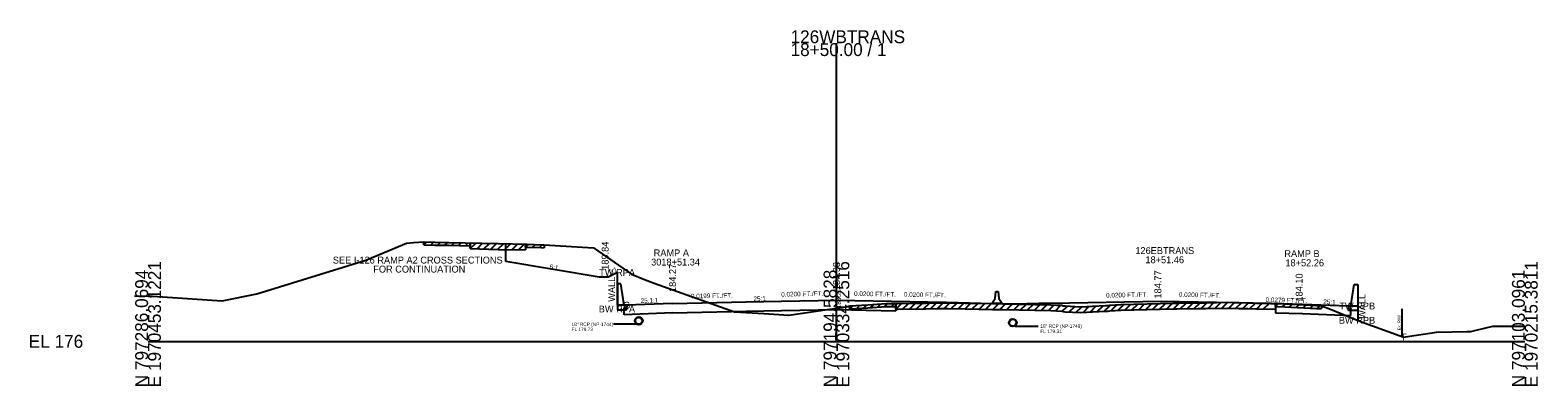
# Model space of a CAD drawing. Extents: x -6494 to 1970605, y -10 to 798140.
# Drawn here: x 974.3 to 1302.8, y 990.3 to 1067.8 of the extents above; entities that cross this region are included whole.
import ezdxf

# ---------------------------------------------------------------- set-up
doc = ezdxf.new("R2010")
doc.units = 0
for name, color, linetype in [('Default', 7, 'Continuous'), ('RD_EX_SU_Misc_TxCode', 7, 'Continuous'), ('RD_GPK_XS_Cell', 7, 'Continuous'), ('RD_Sketch1', 7, 'Continuous'), ('RD_XS_Base', 7, 'Continuous'), ('RD_XS_Box', 7, 'Continuous'), ('RD_XS_EwShp', 7, 'Continuous'), ('RD_XS_ExGround', 7, 'Continuous'), ('RD_XS_ExPaveRet', 7, 'Continuous'), ('RD_XS_ExRW', 7, 'Continuous'), ('RD_XS_MedBWall', 7, 'Continuous'), ('RD_XS_Misc_Line', 7, 'Continuous'), ('RD_XS_Pave', 7, 'Continuous'), ('RD_XS_PaveOvlay', 7, 'Continuous'), ('RD_XS_PaveShd', 7, 'Continuous'), ('RD_XS_Pipe', 7, 'Continuous'), ('RD_XS_TieSlope', 7, 'Continuous'), ('RD_XS_TX_Elev_EX', 7, 'Continuous'), ('RD_XS_TX_Elev_PR', 7, 'Continuous'), ('RD_XS_TX_Misc', 7, 'Continuous'), ('RD_XS_TX_Notes', 7, 'Continuous'), ('RD_XS_TX_Profile', 7, 'Continuous'), ('RD_XS_TX_Slope', 7, 'Continuous'), ('RD_XS_TX_Station', 7, 'Continuous')]:
    doc.layers.add(name, color=color, linetype=linetype)

msp = doc.modelspace()

# ---------------------------------------------------------------- linework, layer by layer
at = {"layer": 'Default'}
for p, q in [((1184, 1008.47), (1184.58, 1009.31)), ((1184.58, 1009.31), (1184.75, 1010.89)), ((1184.75, 1010.89), (1185.25, 1010.89)), ((1185.25, 1010.89), (1185.42, 1009.31)), ((1185.42, 1009.31), (1186, 1008.47)), ((1184, 1008.22), (1184, 1008.47)), ((1186, 1008.22), (1184, 1008.22)), ((1186, 1008.47), (1186, 1008.22))]:
    msp.add_line(p, q, dxfattribs=at)
at = {"layer": 'RD_GPK_XS_Cell'}
for p, q in [((1150, 1000), (1150, 1064.95)), ((1000, 1000), (1150, 1000)), ((1150, 1000), (1300, 1000))]:
    msp.add_line(p, q, dxfattribs=at)
at = {"layer": 'RD_XS_Base'}
for p, q in [((1103.77, 1007.29), (1104.28, 1007.31)), ((1103.77, 1005.81), (1103.77, 1007.29)), ((1114.3, 1006.23), (1103.77, 1005.81)), ((1104.28, 1007.31), (1104.28, 1007.87)), ((1114.3, 1006.23), (1130.33, 1006.55)), ((1130.33, 1006.55), (1138, 1006.7)), ((1138, 1006.7), (1150, 1006.94)), ((1150, 1006.94), (1162.92, 1006.68)), ((1245.7, 1006.21), (1251.57, 1006.06)), ((1251.57, 1006.06), (1262.1, 1005.64)), ((1261.6, 1007.14), (1261.6, 1007.7)), ((1262.1, 1007.12), (1261.6, 1007.14)), ((1262.1, 1005.64), (1262.1, 1007.12))]:
    msp.add_line(p, q, dxfattribs=at)
at = {"layer": 'RD_XS_Box'}
for p, q in [((1102.28, 1007.87), (1102.28, 1015)), ((1104.28, 1007.87), (1102.28, 1007.87)), ((1261.6, 1007.7), (1263.61, 1007.7)), ((1263.61, 1007.7), (1263.61, 1004.58))]:
    msp.add_line(p, q, dxfattribs=at)
at = {"layer": 'RD_XS_ExGround'}
msp.add_line((997.08, 1009.94), (1000, 1009.87), dxfattribs=at)
msp.add_lwpolyline([(1000, 1009.87), (1000.98, 1009.84), (1003.17, 1009.67), (1016.17, 1008.8), (1023.73, 1010.34), (1047.47, 1017.67), (1056.29, 1021.38), (1057.85, 1021.5), (1060.08, 1021.65), (1062.51, 1021.58), (1065.54, 1021.55), (1076.29, 1021.29), (1082.58, 1021.14), (1085.68, 1021.04), (1086.29, 1021.02), (1089.89, 1020.8), (1097.09, 1020.38), (1105.34, 1014.65), (1108.19, 1013.45), (1110.28, 1012.7), (1127.79, 1006.41), (1134.16, 1006.04), (1139.6, 1005.68), (1148.05, 1006.96), (1150, 1007.21), (1151.32, 1007.38), (1152.92, 1007.71), (1156.84, 1007.96), (1160.86, 1008.22), (1163.28, 1008.25), (1169.45, 1008.33), (1172.38, 1008.39), (1173.22, 1008.41), (1174.35, 1008.39), (1178.05, 1008.32), (1184.04, 1008.22), (1184.94, 1008.21), (1186.27, 1008.18), (1196.69, 1007.98), (1197.96, 1007.91), (1199.14, 1007.85), (1199.39, 1007.74), (1199.86, 1007.71), (1203.12, 1007.52), (1204.55, 1007.6), (1205.83, 1007.67), (1208.64, 1007.8), (1209.21, 1007.82), (1209.55, 1007.9), (1211.96, 1008.02), (1223.34, 1008.31), (1223.71, 1008.32), (1224.16, 1008.32), (1228.84, 1008.39), (1230.4, 1008.42), (1235.22, 1008.51), (1237.68, 1008.44), (1239.64, 1008.39), (1241.5, 1008.34), (1247.73, 1008.17), (1254.59, 1007.82), (1255.71, 1007.76), (1257.67, 1006.99), (1264.21, 1004.34), (1272.81, 1001.18), (1273.54, 1000.92), (1274.44, 1001.05), (1280.73, 1001.99), (1287.41, 1002.17), (1288.27, 1002.18), (1289.37, 1002.44), (1293.06, 1003.28), (1295.98, 1003.28), (1300, 1003.28)], dxfattribs=at)
at = {"layer": 'RD_XS_ExPaveRet'}
for p, q in [((1060.08, 1021.02), (1060.08, 1021.65)), ((1060.08, 1021.02), (1062.51, 1020.95)), ((1062.51, 1020.95), (1065.54, 1020.92)), ((1065.54, 1020.92), (1070.16, 1020.81)), ((1070.16, 1020.19), (1070.16, 1021.44)), ((1070.16, 1021.44), (1070.16, 1020.81)), ((1070.16, 1020.19), (1076.29, 1020.04)), ((1076.29, 1020.04), (1082.27, 1019.9)), ((1082.27, 1021.15), (1082.27, 1019.9)), ((1082.27, 1020.53), (1082.27, 1021.15)), ((1082.27, 1020.53), (1082.58, 1020.52)), ((1082.58, 1020.52), (1085.68, 1020.41)), ((1085.68, 1020.41), (1086.29, 1020.39)), ((1086.29, 1021.02), (1086.29, 1020.39)), ((1152.92, 1007.08), (1152.92, 1007.71)), ((1152.92, 1007.08), (1156.84, 1007.33)), ((1156.84, 1007.33), (1160.86, 1007.59)), ((1160.86, 1007.59), (1162.92, 1007.62)), ((1162.92, 1007), (1162.92, 1008.25)), ((1162.92, 1008.25), (1162.92, 1007.62)), ((1162.92, 1007), (1163.28, 1007)), ((1163.28, 1007), (1169.45, 1007.08)), ((1169.45, 1007.08), (1172.38, 1007.14)), ((1172.38, 1007.14), (1173.22, 1007.16)), ((1173.22, 1007.16), (1174.35, 1007.14)), ((1174.35, 1007.14), (1178.05, 1007.07)), ((1178.05, 1007.07), (1184.04, 1006.97)), ((1184.04, 1006.97), (1184.94, 1006.96)), ((1184.94, 1006.96), (1186.27, 1006.93)), ((1186.27, 1006.93), (1196.69, 1006.73)), ((1196.69, 1006.73), (1197.96, 1006.66)), ((1197.96, 1006.66), (1199.14, 1006.6)), ((1199.14, 1006.6), (1199.39, 1006.49)), ((1199.39, 1006.49), (1199.86, 1006.46)), ((1199.86, 1006.46), (1203.12, 1006.27)), ((1203.12, 1006.27), (1204.55, 1006.35)), ((1204.55, 1006.35), (1205.83, 1006.42)), ((1205.83, 1006.42), (1208.64, 1006.55)), ((1208.64, 1006.55), (1209.21, 1006.57)), ((1209.21, 1006.57), (1209.55, 1006.65)), ((1209.55, 1006.65), (1211.96, 1006.77)), ((1211.96, 1006.77), (1223.34, 1007.06)), ((1223.34, 1007.06), (1223.71, 1007.07)), ((1223.71, 1007.07), (1224.16, 1007.07)), ((1224.16, 1007.07), (1228.84, 1007.14)), ((1228.84, 1007.14), (1230.4, 1007.17)), ((1230.4, 1007.17), (1235.22, 1007.26)), ((1235.22, 1007.26), (1237.68, 1007.19)), ((1237.68, 1007.19), (1239.64, 1007.14)), ((1239.64, 1007.14), (1241.5, 1007.09)), ((1241.5, 1007.09), (1245.7, 1006.98)), ((1245.7, 1008.23), (1245.7, 1006.98)), ((1245.7, 1007.6), (1245.7, 1008.23)), ((1245.7, 1007.6), (1247.73, 1007.55)), ((1247.73, 1007.55), (1254.59, 1007.19)), ((1254.59, 1007.19), (1255.71, 1007.14)), ((1255.71, 1007.76), (1255.71, 1007.14))]:
    msp.add_line(p, q, dxfattribs=at)
at = {"layer": 'RD_XS_ExRW'}
msp.add_line((1273.19, 1007.05), (1273.19, 1001.05), dxfattribs=at)
at = {"layer": 'RD_XS_MedBWall'}
for p, q in [((1103.03, 1012.54), (1102.28, 1012.54)), ((1102.28, 1012.54), (1102.28, 1006.87)), ((1103.78, 1007.87), (1103.03, 1012.54)), ((1262.1, 1007.7), (1262.85, 1012.37)), ((1262.85, 1012.37), (1263.6, 1012.37)), ((1263.6, 1012.37), (1263.6, 1006.7)), ((1102.28, 1006.87), (1104.28, 1006.87)), ((1104.28, 1007.87), (1103.78, 1007.87)), ((1104.28, 1006.87), (1104.28, 1007.87)), ((1261.6, 1006.7), (1261.6, 1007.7)), ((1261.6, 1007.7), (1262.1, 1007.7)), ((1263.6, 1006.7), (1261.6, 1006.7))]:
    msp.add_line(p, q, dxfattribs=at)
at = {"layer": 'RD_XS_Misc_Line'}
for p, q in [((1060.08, 1021.02), (1060.69, 1021.63)), ((1061.59, 1020.98), (1062.21, 1021.59)), ((1063.11, 1020.95), (1063.73, 1021.57)), ((1064.62, 1020.93), (1065.24, 1021.55)), ((1066.13, 1020.91), (1066.75, 1021.52)), ((1067.64, 1020.87), (1068.26, 1021.48)), ((1069.16, 1020.84), (1069.77, 1021.45)), ((1070.16, 1020.19), (1071.4, 1021.41)), ((1071.68, 1020.15), (1072.91, 1021.37)), ((1073.19, 1020.12), (1074.42, 1021.34)), ((1074.7, 1020.08), (1075.93, 1021.3)), ((1076.21, 1020.05), (1077.45, 1021.27)), ((1077.73, 1020.01), (1078.96, 1021.23)), ((1079.24, 1019.97), (1080.47, 1021.19)), ((1080.75, 1019.94), (1081.98, 1021.16)), ((1082.27, 1020.53), (1082.88, 1021.13)), ((1083.78, 1020.48), (1084.39, 1021.08)), ((1085.29, 1020.43), (1085.9, 1021.03)), ((1152.92, 1007.08), (1153.59, 1007.75)), ((1154.43, 1007.18), (1155.1, 1007.85)), ((1155.94, 1007.28), (1156.62, 1007.94)), ((1157.45, 1007.37), (1158.13, 1008.04)), ((1158.97, 1007.47), (1159.64, 1008.14)), ((1160.48, 1007.57), (1161.14, 1008.22)), ((1161.99, 1007.61), (1162.63, 1008.24)), ((1162.92, 1007), (1164.19, 1008.26)), ((1164.43, 1007.02), (1165.71, 1008.28)), ((1165.94, 1007.04), (1167.22, 1008.3)), ((1167.45, 1007.06), (1168.73, 1008.32)), ((1168.97, 1007.07), (1170.25, 1008.35)), ((1170.48, 1007.1), (1171.77, 1008.38)), ((1171.99, 1007.13), (1173.28, 1008.41)), ((1173.51, 1007.15), (1174.74, 1008.38)), ((1175.02, 1007.13), (1176.26, 1008.35)), ((1176.53, 1007.1), (1177.77, 1008.33)), ((1178.04, 1007.07), (1179.28, 1008.3)), ((1179.56, 1007.05), (1180.8, 1008.28)), ((1181.07, 1007.02), (1182.31, 1008.25)), ((1182.58, 1007), (1183.82, 1008.23)), ((1184.09, 1006.97), (1185.33, 1008.2)), ((1185.61, 1006.95), (1186.84, 1008.17)), ((1187.12, 1006.91), (1188.35, 1008.14)), ((1188.63, 1006.88), (1189.87, 1008.11)), ((1190.14, 1006.86), (1191.38, 1008.08)), ((1191.66, 1006.83), (1192.89, 1008.05)), ((1193.17, 1006.8), (1194.41, 1008.02)), ((1194.68, 1006.77), (1195.92, 1007.99)), ((1196.19, 1006.74), (1197.41, 1007.94)), ((1197.71, 1006.68), (1198.9, 1007.86)), ((1199.22, 1006.57), (1200.35, 1007.68)), ((1200.73, 1006.41), (1201.92, 1007.59)), ((1202.24, 1006.32), (1203.47, 1007.54)), ((1203.76, 1006.31), (1205.09, 1007.63)), ((1205.27, 1006.39), (1206.6, 1007.71)), ((1206.78, 1006.47), (1208.1, 1007.77)), ((1208.3, 1006.53), (1209.69, 1007.91)), ((1209.81, 1006.67), (1211.13, 1007.98)), ((1211.32, 1006.74), (1212.63, 1008.03)), ((1212.83, 1006.79), (1214.13, 1008.07)), ((1214.35, 1006.83), (1215.64, 1008.11)), ((1215.86, 1006.87), (1217.15, 1008.15)), ((1217.37, 1006.9), (1218.66, 1008.19)), ((1218.88, 1006.94), (1220.18, 1008.23)), ((1220.4, 1006.98), (1221.69, 1008.26)), ((1221.91, 1007.02), (1223.2, 1008.3)), ((1223.42, 1007.06), (1224.7, 1008.33)), ((1224.93, 1007.08), (1226.21, 1008.35)), ((1226.45, 1007.11), (1227.73, 1008.38)), ((1227.96, 1007.13), (1229.24, 1008.4)), ((1229.47, 1007.15), (1230.76, 1008.43)), ((1230.98, 1007.18), (1232.27, 1008.45)), ((1232.5, 1007.21), (1233.78, 1008.48)), ((1234.01, 1007.24), (1235.29, 1008.5)), ((1235.52, 1007.25), (1236.75, 1008.47)), ((1237.03, 1007.21), (1238.26, 1008.42)), ((1238.55, 1007.17), (1239.77, 1008.38)), ((1240.06, 1007.13), (1241.29, 1008.35)), ((1241.57, 1007.09), (1242.8, 1008.31)), ((1243.09, 1007.05), (1244.31, 1008.27)), ((1245.7, 1007.6), (1246.32, 1008.21)), ((1247.22, 1007.56), (1247.83, 1008.17)), ((1248.73, 1007.5), (1249.33, 1008.09)), ((1250.24, 1007.42), (1250.84, 1008.01)), ((1251.76, 1007.34), (1252.35, 1007.93)), ((1253.27, 1007.26), (1253.87, 1007.86)), ((1254.78, 1007.19), (1255.38, 1007.78))]:
    msp.add_line(p, q, dxfattribs=at)
at = {"layer": 'RD_XS_Pave'}
for p, q in [((1138, 1008.74), (1150, 1008.98)), ((1150, 1008.98), (1174, 1008.5)), ((1196.79, 1008.29), (1220.79, 1008.77)), ((1220.79, 1008.77), (1232.79, 1008.53)), ((1114.3, 1008.27), (1130.33, 1008.59)), ((1232.79, 1008.53), (1244.79, 1008.29)), ((1244.79, 1008.29), (1251.57, 1008.1))]:
    msp.add_line(p, q, dxfattribs=at)
at = {"layer": 'RD_XS_PaveOvlay'}
for p, q in [((1162.92, 1008.25), (1163.28, 1008.25)), ((1162.92, 1008.25), (1162.92, 1006.68)), ((1163.28, 1008.25), (1169.45, 1008.33)), ((1169.45, 1008.33), (1172.38, 1008.39)), ((1172.38, 1008.39), (1173.22, 1008.41)), ((1173.22, 1008.41), (1174.35, 1008.39)), ((1174.35, 1008.39), (1178.05, 1008.32)), ((1178.05, 1008.32), (1184.04, 1008.22)), ((1184.04, 1008.22), (1184.94, 1008.21)), ((1184.94, 1008.21), (1186.27, 1008.18)), ((1186.27, 1008.18), (1196.69, 1007.98)), ((1196.69, 1007.98), (1197.96, 1007.91)), ((1197.96, 1007.91), (1199.14, 1007.85)), ((1199.14, 1007.85), (1199.39, 1007.74)), ((1199.39, 1007.74), (1199.86, 1007.71)), ((1199.86, 1007.71), (1203.12, 1007.52)), ((1203.12, 1007.52), (1204.55, 1007.6)), ((1204.55, 1007.6), (1205.83, 1007.67)), ((1205.83, 1007.67), (1208.64, 1007.8)), ((1208.64, 1007.8), (1209.21, 1007.82)), ((1209.21, 1007.82), (1209.55, 1007.9)), ((1209.55, 1007.9), (1211.96, 1008.02)), ((1211.96, 1008.02), (1223.34, 1008.31)), ((1223.34, 1008.31), (1223.71, 1008.32)), ((1223.71, 1008.32), (1224.16, 1008.32)), ((1224.16, 1008.32), (1228.84, 1008.39)), ((1228.84, 1008.39), (1230.4, 1008.42)), ((1230.4, 1008.42), (1235.22, 1008.51)), ((1235.22, 1008.51), (1237.68, 1008.44)), ((1237.68, 1008.44), (1239.64, 1008.39)), ((1239.64, 1008.39), (1241.5, 1008.34)), ((1241.5, 1008.34), (1245.7, 1008.23)), ((1245.7, 1008.23), (1245.7, 1006.21))]:
    msp.add_line(p, q, dxfattribs=at)
at = {"layer": 'RD_XS_PaveShd'}
for p, q in [((1130.33, 1008.59), (1138, 1008.74)), ((1114.3, 1008.27), (1104.28, 1007.87)), ((1174, 1008.5), (1184, 1008.22)), ((1188.79, 1008.13), (1183.82, 1008.23)), ((1196.79, 1008.29), (1188.79, 1008.13)), ((1251.57, 1008.1), (1261.6, 1007.7))]:
    msp.add_line(p, q, dxfattribs=at)
at = {"layer": 'RD_XS_Pipe'}
for p, q in [((1106.43, 1003.73), (1101.43, 1003.73)), ((1188.93, 1003.31), (1193.93, 1003.31))]:
    msp.add_line(p, q, dxfattribs=at)
for centre, radius in [((1106.93, 1004.48), 0.85), ((1106.93, 1004.48), 0.75), ((1188.43, 1004.06), 0.85), ((1188.43, 1004.06), 0.75)]:
    msp.add_circle(centre, radius, dxfattribs=at)
at = {"layer": 'RD_XS_TieSlope'}
for p, q in [((1077.98, 1017.39), (1077.98, 1021.25)), ((1098.28, 1014), (1077.98, 1017.39)), ((1100.28, 1014), (1098.28, 1014)), ((1102.28, 1015), (1100.28, 1014))]:
    msp.add_line(p, q, dxfattribs=at)

# ---------------------------------------------------------------- texts
at = {"layer": 'RD_EX_SU_Misc_TxCode'}
msp.add_text('G', height=1.5, dxfattribs=at).set_placement((1103.53, 1007.12))
at = {"layer": 'RD_GPK_XS_Cell'}
for s, p in [('126WBTRANS', (1140, 1064.95)), ('18+50.00 / 1', (1140, 1062.15)), ('EL 176', (974, 998.6))]:
    msp.add_text(s, height=2.8, dxfattribs=at).set_placement(p)
for s, p in [('N 797286.0694', (1000, 990)), ('E 1970453.1221', (1002.8, 990)), ('N 797194.5828', (1150, 990)), ('E 1970334.2516', (1152.8, 990)), ('N 797103.0961', (1300, 990)), ('E 1970215.3811', (1302.8, 990))]:
    msp.add_text(s, height=2.8, rotation=90, dxfattribs=at).set_placement(p)
at = {"layer": 'RD_Sketch1'}
msp.add_text('T', height=1.5, dxfattribs=at).set_placement((1272.99, 1000.17))
at = {"layer": 'RD_XS_EwShp'}
for s, p in [('TW RPA', (1098.31, 1014.25)), ('BW RPA', (1098.21, 1006.29)), ('TW RPB', (1259.58, 1006.95)), ('BW RPB', (1259.48, 1003.83))]:
    msp.add_text(s, height=1.5, dxfattribs=at).set_placement(p)
at = {"layer": 'RD_XS_ExRW'}
msp.add_text('Ex. R/W ', height=0.65, rotation=90, dxfattribs=at).set_placement((1272.94, 1002.43))
at = {"layer": 'RD_XS_Pipe'}
for s, p in [('18" RCP (NP-1744)', (1092.28, 1003.35)), ('FL 179.73', (1092.28, 1002.23)), ('18" RCP (NP-1749)', (1194.43, 1002.94)), ('FL 179.31', (1194.43, 1001.81))]:
    msp.add_text(s, height=0.75, dxfattribs=at).set_placement(p)
at = {"layer": 'RD_XS_TX_Elev_EX'}
msp.add_text('183.21', height=1, rotation=90, dxfattribs=at).set_placement((1151, 1007.21))
at = {"layer": 'RD_XS_TX_Elev_PR'}
for s, p in [('184.27', (1115.05, 1010.75)), ('184.98', (1150.75, 1011.15)), (' 184.77', (1220.79, 1008.77)), (' 184.10', (1251.57, 1008.1))]:
    msp.add_text(s, height=1.5, rotation=90, dxfattribs=at).set_placement(p)
at = {"layer": 'RD_XS_TX_Misc'}
msp.add_text('189.84', height=1.5, rotation=90, dxfattribs=at).set_placement((1100.35, 1015.58))
at = {"layer": 'RD_XS_TX_Notes'}
for s, p in [('SEE I-126 RAMP A2 CROSS SECTIONS', (1040.26, 1016.95)), ('FOR CONTINUATION', (1049.07, 1014.98))]:
    msp.add_text(s, height=1.5, dxfattribs=at).set_placement(p)
for p in [(1101.77, 1008.62), (1265.27, 1004.88)]:
    msp.add_text('WALL', height=1.5, rotation=90, dxfattribs=at).set_placement(p)
at = {"layer": 'RD_XS_TX_Profile'}
for rotation, p in [(2.2906, (1131.94, 1008.75)), (357.7094, (1256.08, 1008.14))]:
    msp.add_text('25:1', height=1, rotation=rotation, dxfattribs=at).set_placement(p)
at = {"layer": 'RD_XS_TX_Slope'}
for s, rotation, p in [('6:1', 350.5377, (1087.42, 1015.81)), ('2:1', 26.5651, (1100.67, 1014.52)), ('25.1:1', 2.286, (1107.36, 1008.34)), ('0.0199 FT./FT.', 1.1383, (1118.3, 1009.35)), ('0.0200 FT./FT.', 1.1458, (1137.98, 1009.74)), ('0.0200 FT./FT.', 358.8542, (1153.83, 1009.91)), ('0.0200 FT./FT.', 358.8542, (1164.69, 1009.73)), ('0.0200 FT./FT.', 1.1456, (1208.77, 1009.53)), ('0.0200 FT./FT.', 358.8542, (1224.61, 1009.7)), ('0.0279 FT./FT.', 358.3994, (1243.5, 1008.59))]:
    msp.add_text(s, height=1, rotation=rotation, dxfattribs=at).set_placement(p)
at = {"layer": 'RD_XS_TX_Station'}
for s, p in [('RAMP A', (1110.18, 1018.52)), ('126EBTRANS', (1215.14, 1019.02)), ('18+51.46', (1217.33, 1017.02)), ('RAMP B', (1247.6, 1018.35)), ('3018+51.34', (1109.62, 1016.52)), ('18+52.26', (1247.83, 1016.35))]:
    msp.add_text(s, height=1.5, dxfattribs=at).set_placement(p)

doc.saveas('drawing.dxf')
